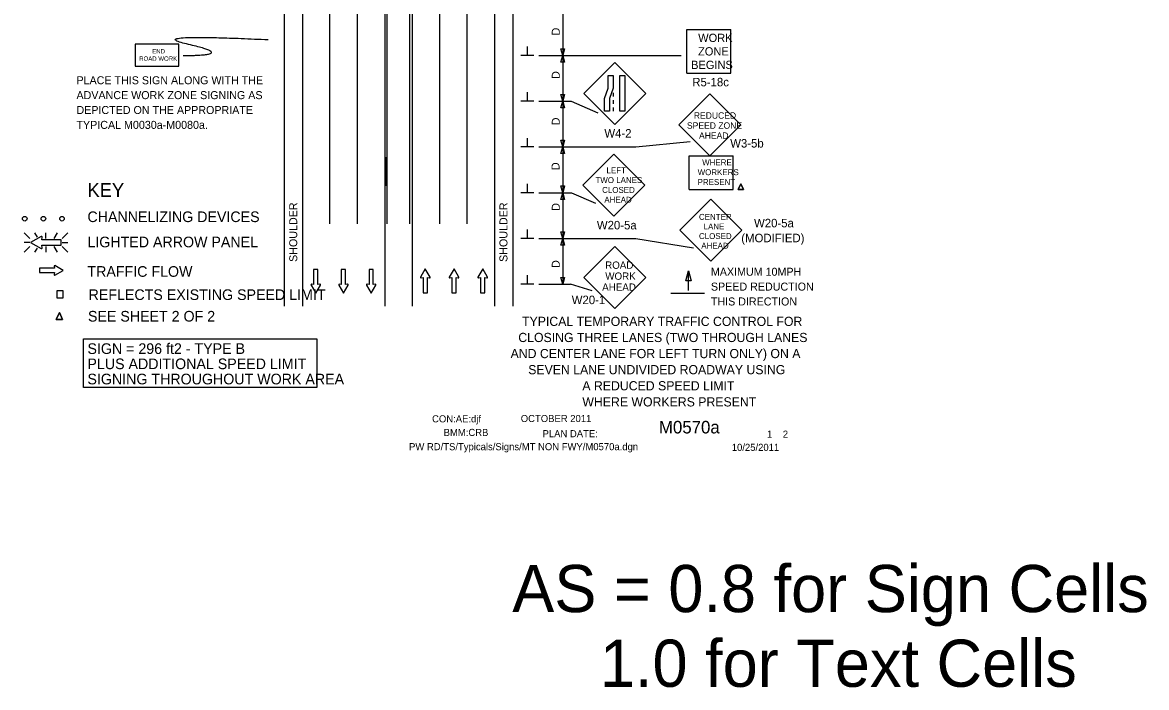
# Model space of a CAD drawing. Extents: x 16724 to 18475, y 5726 to 6929.
# Drawn here: x 16732 to 17716, y 5726 to 6308 of the extents above; entities that cross this region are included whole.
import ezdxf

# ---------------------------------------------------------------- set-up
doc = ezdxf.new("R2010")
doc.units = 0
for name, color, linetype in [('ALI_LEGAL_EX', 7, 'Continuous'), ('BORDER', 7, 'Continuous'), ('BORDER_SIGNAL_WO', 7, 'Continuous'), ('Level 3', 7, 'Continuous'), ('MT_SCRATCH_LEVEL_E', 7, 'Continuous'), ('PAVT_EDGE_EX', 7, 'Continuous'), ('TRAFFIC_SIGNS_PR', 7, 'Continuous'), ('TYPICAL_TEXT_DIMEN_EX', 7, 'Continuous'), ('TYPICAL_TEXT_DIMEN_PR', 7, 'Continuous')]:
    doc.layers.add(name, color=color, linetype=linetype)

msp = doc.modelspace()

# ---------------------------------------------------------------- linework, layer by layer
at = {"layer": 'ALI_LEGAL_EX'}
for p, q in [((17001.36, 6131.68), (17001.36, 6928.96)), ((17025.36, 6131.68), (17025.36, 6928.96)), ((17051.36, 6131.68), (17051.36, 6928.96)), ((17071.36, 6131.68), (17071.36, 6928.96)), ((17097.36, 6131.68), (17097.36, 6928.96)), ((17121.36, 6131.68), (17121.36, 6928.96))]:
    msp.add_line(p, q, dxfattribs=at)
for points in [[(17001.36, 6231.68), (17001.36, 6256.68)], [(17025.36, 6231.68), (17025.36, 6256.68)], [(17051.36, 6231.68), (17051.36, 6256.68)], [(17071.36, 6231.68), (17071.36, 6256.68)], [(17097.36, 6231.68), (17097.36, 6256.68)], [(17121.36, 6231.68), (17121.36, 6256.68)], [(17001.36, 6131.68), (17001.36, 6156.68)], [(17025.36, 6131.68), (17025.36, 6156.68)], [(17051.36, 6131.68), (17051.36, 6156.68)], [(17071.36, 6131.68), (17071.36, 6156.68)], [(17097.36, 6131.68), (17097.36, 6156.68)], [(17121.36, 6131.68), (17121.36, 6156.68)]]:
    msp.add_lwpolyline(points, dxfattribs=at)
at = {"layer": 'Level 3'}
msp.add_line((17268.9, 6118.89), (17319.36, 6110.64), dxfattribs=at)
at = {"layer": 'MT_SCRATCH_LEVEL_E'}
for p, q in [((16760.32, 6092.83), (16747.06, 6092.83)), ((16747.06, 6092.83), (16747.06, 6089.09)), ((16760.32, 6092.83), (16747.06, 6092.83)), ((16747.06, 6092.83), (16747.06, 6089.09)), ((16747.06, 6089.09), (16760.32, 6089.09)), ((16747.06, 6089.09), (16760.32, 6089.09)), ((16760, 6094.61), (16760.32, 6092.83)), ((16760, 6094.61), (16760.32, 6092.83)), ((16760.32, 6089.09), (16760, 6087.31)), ((16760.32, 6089.09), (16760, 6087.31)), ((16767.93, 6090.98), (16760.69, 6095.09)), ((16767.93, 6090.98), (16760.69, 6095.09)), ((16760.69, 6086.83), (16767.93, 6090.98)), ((16760.69, 6086.83), (16767.93, 6090.98)), ((16990.77, 6091.79), (16987.03, 6091.79)), ((16987.03, 6091.79), (16987.03, 6078.53)), ((16990.77, 6091.79), (16987.03, 6091.79)), ((16987.03, 6091.79), (16987.03, 6078.53)), ((16990.77, 6078.53), (16990.77, 6091.79)), ((16990.77, 6078.53), (16990.77, 6091.79)), ((17015.03, 6091.79), (17011.28, 6091.79)), ((17011.28, 6091.79), (17011.28, 6078.53)), ((17015.03, 6091.79), (17011.28, 6091.79)), ((17011.28, 6091.79), (17011.28, 6078.53)), ((17015.03, 6078.53), (17015.03, 6091.79)), ((17015.03, 6078.53), (17015.03, 6091.79)), ((17039.28, 6091.79), (17035.54, 6091.79)), ((17035.54, 6091.79), (17035.54, 6078.53)), ((17039.28, 6091.79), (17035.54, 6091.79)), ((17035.54, 6091.79), (17035.54, 6078.53)), ((17039.28, 6078.53), (17039.28, 6091.79)), ((17039.28, 6078.53), (17039.28, 6091.79)), ((17084.79, 6092.25), (17080.68, 6085.01)), ((17084.79, 6092.25), (17080.68, 6085.01)), ((17088.94, 6085.01), (17084.79, 6092.25)), ((17088.94, 6085.01), (17084.79, 6092.25)), ((17109.88, 6092.25), (17105.77, 6085.01)), ((17109.88, 6092.25), (17105.77, 6085.01)), ((17114.03, 6085.01), (17109.88, 6092.25)), ((17114.03, 6085.01), (17109.88, 6092.25)), ((17134.97, 6092.25), (17130.86, 6085.01)), ((17134.97, 6092.25), (17130.86, 6085.01)), ((17139.12, 6085.01), (17134.97, 6092.25)), ((17139.12, 6085.01), (17134.97, 6092.25)), ((16984.77, 6078.16), (16988.92, 6070.92)), ((16984.77, 6078.16), (16988.92, 6070.92)), ((16987.03, 6078.53), (16985.25, 6078.85)), ((16987.03, 6078.53), (16985.25, 6078.85)), ((16988.92, 6070.92), (16993.03, 6078.16)), ((16988.92, 6070.92), (16993.03, 6078.16)), ((16992.55, 6078.85), (16990.77, 6078.53)), ((16992.55, 6078.85), (16990.77, 6078.53)), ((17009.03, 6078.16), (17013.17, 6070.92)), ((17009.03, 6078.16), (17013.17, 6070.92)), ((17011.28, 6078.53), (17009.51, 6078.85)), ((17011.28, 6078.53), (17009.51, 6078.85)), ((17013.17, 6070.92), (17017.28, 6078.16)), ((17013.17, 6070.92), (17017.28, 6078.16)), ((17016.8, 6078.85), (17015.03, 6078.53)), ((17016.8, 6078.85), (17015.03, 6078.53)), ((17033.28, 6078.16), (17037.43, 6070.92)), ((17033.28, 6078.16), (17037.43, 6070.92)), ((17035.54, 6078.53), (17033.76, 6078.85)), ((17035.54, 6078.53), (17033.76, 6078.85)), ((17037.43, 6070.92), (17041.54, 6078.16)), ((17037.43, 6070.92), (17041.54, 6078.16)), ((17041.06, 6078.85), (17039.28, 6078.53)), ((17041.06, 6078.85), (17039.28, 6078.53)), ((17081.16, 6084.32), (17082.94, 6084.64)), ((17081.16, 6084.32), (17082.94, 6084.64)), ((17082.94, 6084.64), (17082.94, 6071.38)), ((17082.94, 6084.64), (17082.94, 6071.38)), ((17086.68, 6071.38), (17086.68, 6084.64)), ((17086.68, 6084.64), (17088.46, 6084.32)), ((17086.68, 6071.38), (17086.68, 6084.64)), ((17086.68, 6084.64), (17088.46, 6084.32)), ((17106.25, 6084.32), (17108.03, 6084.64)), ((17106.25, 6084.32), (17108.03, 6084.64)), ((17108.03, 6084.64), (17108.03, 6071.38)), ((17108.03, 6084.64), (17108.03, 6071.38)), ((17111.77, 6071.38), (17111.77, 6084.64)), ((17111.77, 6084.64), (17113.55, 6084.32)), ((17111.77, 6071.38), (17111.77, 6084.64)), ((17111.77, 6084.64), (17113.55, 6084.32)), ((17131.34, 6084.32), (17133.12, 6084.64)), ((17131.34, 6084.32), (17133.12, 6084.64)), ((17133.12, 6084.64), (17133.12, 6071.38)), ((17133.12, 6084.64), (17133.12, 6071.38)), ((17136.86, 6071.38), (17136.86, 6084.64)), ((17136.86, 6084.64), (17138.64, 6084.32)), ((17136.86, 6071.38), (17136.86, 6084.64)), ((17136.86, 6084.64), (17138.64, 6084.32)), ((17082.94, 6071.38), (17086.68, 6071.38)), ((17082.94, 6071.38), (17086.68, 6071.38)), ((17108.03, 6071.38), (17111.77, 6071.38)), ((17108.03, 6071.38), (17111.77, 6071.38)), ((17133.12, 6071.38), (17136.86, 6071.38)), ((17133.12, 6071.38), (17136.86, 6071.38))]:
    msp.add_line(p, q, dxfattribs=at)
for centre, start, end in [((16760.46, 6094.68), 60.42484, 189.96381), ((16760.46, 6094.68), 60.42484, 189.96381), ((16760.46, 6087.24), 170.03619, 299.77312), ((16760.46, 6087.24), 170.03619, 299.77312), ((16985.18, 6078.38), 80.03619, 209.77312), ((16985.18, 6078.38), 80.03619, 209.77312), ((16992.62, 6078.39), 330.42484, 99.96381), ((16992.62, 6078.39), 330.42484, 99.96381), ((17009.44, 6078.38), 80.03619, 209.77312), ((17009.44, 6078.38), 80.03619, 209.77312), ((17016.88, 6078.39), 330.42484, 99.96381), ((17016.88, 6078.39), 330.42484, 99.96381), ((17033.69, 6078.38), 80.03619, 209.77312), ((17033.69, 6078.38), 80.03619, 209.77312), ((17041.13, 6078.39), 330.42484, 99.96381), ((17041.13, 6078.39), 330.42484, 99.96381), ((17081.09, 6084.78), 150.42484, 279.96381), ((17081.09, 6084.78), 150.42484, 279.96381), ((17088.53, 6084.78), 260.03619, 29.77312), ((17088.53, 6084.78), 260.03619, 29.77312), ((17106.18, 6084.78), 150.42484, 279.96381), ((17106.18, 6084.78), 150.42484, 279.96381), ((17113.62, 6084.78), 260.03619, 29.77312), ((17113.62, 6084.78), 260.03619, 29.77312), ((17131.27, 6084.78), 150.42484, 279.96381), ((17131.27, 6084.78), 150.42484, 279.96381), ((17138.71, 6084.78), 260.03619, 29.77312), ((17138.71, 6084.78), 260.03619, 29.77312)]:
    msp.add_arc(centre, 0.463, start, end, dxfattribs=at)
at = {"layer": 'PAVT_EDGE_EX'}
for p, q in [((16961.36, 6924.76), (16961.36, 6059.7)), ((16977.36, 6924.76), (16977.36, 6059.7)), ((17049.36, 6924.76), (17049.36, 6059.7)), ((17073.36, 6924.76), (17073.36, 6059.7)), ((17145.36, 6924.76), (17145.36, 6059.7)), ((17161.36, 6924.76), (17161.36, 6059.7))]:
    msp.add_line(p, q, dxfattribs=at)
for points in [[(17025.36, 6164.93), (17025.36, 6189.93)], [(17050.36, 6164.93), (17050.36, 6189.93)]]:
    msp.add_lwpolyline(points, dxfattribs=at)
at = {"layer": 'TRAFFIC_SIGNS_PR'}
for p, q in [((17313.56, 6263.32), (17313.56, 6301.72)), ((17313.56, 6301.72), (17351.96, 6301.72)), ((17351.96, 6263.32), (17351.96, 6301.72)), ((17250.5, 6272.84), (17223.35, 6245.69)), ((17277.65, 6245.69), (17250.5, 6272.84)), ((17313.56, 6263.32), (17351.96, 6263.32)), ((17223.35, 6245.69), (17250.5, 6218.54)), ((17249.25, 6246.18), (17249.25, 6242.98)), ((17250.5, 6218.54), (17277.65, 6245.69)), ((17333.65, 6245.44), (17306.5, 6218.29)), ((17360.8, 6218.29), (17333.65, 6245.44)), ((17249.25, 6239.78), (17249.25, 6236.58)), ((17249.25, 6233.38), (17249.25, 6230.18)), ((17306.5, 6218.29), (17333.65, 6191.14)), ((17333.65, 6191.14), (17360.8, 6218.29)), ((17249.78, 6192.54), (17222.62, 6165.39)), ((17276.93, 6165.39), (17249.78, 6192.54)), ((17315.7, 6191.14), (17354.1, 6191.14)), ((17315.7, 6161.82), (17315.7, 6191.14)), ((17354.1, 6161.82), (17354.1, 6191.14)), ((17222.62, 6165.39), (17249.78, 6138.23)), ((17249.78, 6138.23), (17276.93, 6165.39)), ((17315.7, 6161.82), (17354.1, 6161.82)), ((17334.64, 6153.3), (17307.49, 6126.15)), ((17361.8, 6126.15), (17334.64, 6153.3)), ((16733.68, 6123.85), (16738.62, 6118.92)), ((16745.44, 6120.03), (16743.24, 6123.85)), ((16752.76, 6118.92), (16752.76, 6123.85)), ((16760, 6118.92), (16762.85, 6123.85)), ((16766.91, 6118.92), (16771.85, 6123.85)), ((17307.49, 6126.15), (17334.64, 6098.99)), ((17334.64, 6098.99), (17361.8, 6126.15)), ((16738.62, 6115.36), (16733.68, 6115.36)), ((16733.68, 6106.87), (16738.62, 6111.8)), ((16743.19, 6106.87), (16745.31, 6110.53)), ((16752.76, 6111.8), (16752.76, 6106.87)), ((16762.89, 6106.87), (16760.04, 6111.8)), ((16766.91, 6115.36), (16771.85, 6115.36)), ((16766.91, 6111.8), (16771.85, 6106.87)), ((17250.59, 6111.96), (17223.44, 6084.81)), ((17277.74, 6084.81), (17250.59, 6111.96)), ((17223.44, 6084.81), (17250.59, 6057.66)), ((17250.59, 6057.66), (17277.74, 6084.81))]:
    msp.add_line(p, q, dxfattribs=at)
for points in [[(16830.82, 6269.48), (16869.22, 6269.48), (16869.22, 6288.68), (16830.82, 6288.68)], [(17249.25, 6261.43), (17249.25, 6250.25), (17245.91, 6241.36), (17245.91, 6230.18), (17241.42, 6230.18), (17241.42, 6241.36), (17244.76, 6250.25), (17244.76, 6261.43)], [(17259.39, 6261.43), (17259.39, 6230.18), (17254.9, 6230.18), (17254.9, 6261.43)], [(16762.39, 6066.92), (16767.98, 6066.92), (16767.98, 6073.09), (16762.39, 6073.09)]]:
    msp.add_lwpolyline(points, close=True, dxfattribs=at)
for points in [[(17360.85, 6166.76), (17358.62, 6161.82)], [(17358.62, 6161.82), (17360.85, 6166.76)], [(17363.09, 6161.82), (17360.85, 6166.76)], [(17360.85, 6166.76), (17363.09, 6161.82)], [(17358.62, 6161.82), (17363.09, 6161.82)], [(17363.09, 6161.82), (17358.62, 6161.82)], [(16748.69, 6120.64), (16739.4, 6115.36), (16748.69, 6110.04)], [(16749.57, 6110.67), (16749.17, 6112.93), (16766.18, 6112.93), (16766.18, 6117.74), (16749.17, 6117.74), (16749.57, 6120.02)], [(16764.63, 6054.22), (16761.84, 6048.05)], [(16761.84, 6048.05), (16764.63, 6054.22)], [(16767.43, 6048.05), (16764.63, 6054.22)], [(16764.63, 6054.22), (16767.43, 6048.05)], [(16761.84, 6048.05), (16767.43, 6048.05)], [(16767.43, 6048.05), (16761.84, 6048.05)]]:
    msp.add_lwpolyline(points, dxfattribs=at)
for centre in [(16734.3, 6136.14), (16750.6, 6136.14), (16766.9, 6136.14)]:
    msp.add_circle(centre, 2, dxfattribs=at)
for centre, radius, start, end in [((16748.98, 6120.11), 0.598, 350.73078, 118.89165), ((16748.98, 6110.56), 0.597, 241.48329, 9.95933)]:
    msp.add_arc(centre, radius, start, end, dxfattribs=at)
msp.add_open_spline([(16872.81, 6278.85), (16920.05, 6278.85), (16835.03, 6298.2), (16947.32, 6292.71)], degree=2, dxfattribs=at)
at = {"layer": 'TYPICAL_TEXT_DIMEN_EX'}
msp.add_lwpolyline([(16785.8, 6031.01), (16989.79, 6031.01), (16989.79, 5988.44), (16785.8, 5988.44)], close=True, dxfattribs=at)
at = {"layer": 'TYPICAL_TEXT_DIMEN_PR'}
for p, q in [((17204.99, 6318.89), (17204.99, 6278.89)), ((17174.11, 6278.89), (17174.11, 6286.68)), ((17204.99, 6278.89), (17203.42, 6284.75)), ((17203.42, 6284.75), (17204.99, 6284.75)), ((17204.99, 6284.75), (17206.56, 6284.75)), ((17206.56, 6284.75), (17204.99, 6278.89)), ((17179.74, 6278.89), (17168.49, 6278.89)), ((17183.99, 6278.89), (17308.55, 6278.89)), ((17203.42, 6273.03), (17204.99, 6278.89)), ((17204.99, 6278.89), (17204.99, 6198.89)), ((17204.99, 6278.89), (17206.56, 6273.03)), ((17204.99, 6273.03), (17203.42, 6273.03)), ((17206.56, 6273.03), (17204.99, 6273.03)), ((17174.11, 6238.89), (17174.11, 6246.68)), ((17179.74, 6238.89), (17168.49, 6238.89)), ((17183.99, 6238.89), (17212.39, 6238.89)), ((17204.99, 6238.89), (17203.42, 6244.75)), ((17203.42, 6244.75), (17204.99, 6244.75)), ((17203.42, 6233.03), (17204.99, 6238.89)), ((17204.99, 6244.75), (17206.56, 6244.75)), ((17206.56, 6244.75), (17204.99, 6238.89)), ((17204.99, 6238.89), (17206.56, 6233.03)), ((17212.39, 6238.89), (17235.63, 6228.67)), ((17204.99, 6233.03), (17203.42, 6233.03)), ((17206.56, 6233.03), (17204.99, 6233.03)), ((17204.99, 6218.89), (17204.99, 6168.89)), ((17174.11, 6198.89), (17174.11, 6206.68)), ((17179.74, 6198.89), (17168.49, 6198.89)), ((17183.99, 6198.89), (17268.9, 6198.89)), ((17204.99, 6198.89), (17203.42, 6204.75)), ((17203.42, 6204.75), (17204.99, 6204.75)), ((17203.42, 6193.03), (17204.99, 6198.89)), ((17204.99, 6204.75), (17206.56, 6204.75)), ((17206.56, 6204.75), (17204.99, 6198.89)), ((17204.99, 6198.89), (17206.56, 6193.03)), ((17268.9, 6198.89), (17316.64, 6203.69)), ((17204.99, 6193.03), (17203.42, 6193.03)), ((17206.56, 6193.03), (17204.99, 6193.03)), ((17174.11, 6158.89), (17174.11, 6166.68)), ((17204.99, 6168.89), (17204.99, 6118.89)), ((17179.74, 6158.89), (17168.49, 6158.89)), ((17183.99, 6158.89), (17212.82, 6158.89)), ((17204.99, 6158.89), (17203.42, 6164.75)), ((17203.42, 6164.75), (17204.99, 6164.75)), ((17203.42, 6153.03), (17204.99, 6158.89)), ((17204.99, 6164.75), (17206.56, 6164.75)), ((17206.56, 6164.75), (17204.99, 6158.89)), ((17204.99, 6158.89), (17206.56, 6153.03)), ((17212.82, 6158.89), (17233.78, 6149.67)), ((17204.99, 6153.03), (17203.42, 6153.03)), ((17206.56, 6153.03), (17204.99, 6153.03)), ((17179.74, 6118.89), (17168.49, 6118.89)), ((17174.11, 6118.89), (17174.11, 6126.68)), ((17183.99, 6118.89), (17268.9, 6118.89)), ((17204.99, 6118.89), (17203.42, 6124.75)), ((17203.42, 6124.75), (17204.99, 6124.75)), ((17203.42, 6113.03), (17204.99, 6118.89)), ((17204.99, 6124.75), (17206.56, 6124.75)), ((17206.56, 6124.75), (17204.99, 6118.89)), ((17204.99, 6118.89), (17204.99, 6078.89)), ((17204.99, 6118.89), (17206.56, 6113.03)), ((17204.99, 6113.03), (17203.42, 6113.03)), ((17206.56, 6113.03), (17204.99, 6113.03)), ((17312.61, 6081.69), (17314.97, 6090.49)), ((17314.97, 6073.36), (17314.97, 6090.49)), ((17314.97, 6090.49), (17317.32, 6081.69)), ((17179.74, 6078.89), (17168.49, 6078.89)), ((17174.11, 6078.89), (17174.11, 6086.68)), ((17183.99, 6078.89), (17211.79, 6078.89)), ((17204.99, 6078.89), (17203.42, 6084.75)), ((17203.42, 6084.75), (17204.99, 6084.75)), ((17204.99, 6084.75), (17206.56, 6084.75)), ((17206.56, 6084.75), (17204.99, 6078.89)), ((17230.7, 6073.14), (17211.79, 6078.89)), ((17314.97, 6081.69), (17312.61, 6081.69)), ((17317.32, 6081.69), (17314.97, 6081.69)), ((17329.14, 6070.86), (17299.7, 6070.86))]:
    msp.add_line(p, q, dxfattribs=at)

# ---------------------------------------------------------------- texts
at = {"layer": 'BORDER'}
for s, height, p in [('TYPICAL TEMPORARY TRAFFIC CONTROL FOR', 8.0313, (17169.43, 6042.37)), ('CLOSING THREE LANES (TWO THROUGH LANES', 8.0313, (17166.13, 6028.29)), ('AND CENTER LANE FOR LEFT TURN ONLY) ON A', 8.0313, (17159.4, 6014.22)), ('SEVEN LANE UNDIVIDED ROADWAY USING ', 8.0313, (17174.82, 6000.14)), ('A REDUCED SPEED LIMIT', 8.0313, (17222.18, 5986.06)), ('WHERE WORKERS PRESENT', 8.0313, (17222.18, 5971.99)), ('PLAN DATE:', 6.2, (17187.35, 5945.07))]:
    msp.add_text(s, height=height, dxfattribs=at).set_placement(p)
at = {"layer": 'BORDER_SIGNAL_WO'}
for s, height, p in [('CON:AE:djf', 6.2, (17090.69, 5958.06)), ('    OCTOBER 2011    ', 6.2, (17159.08, 5958.34)), ('BMM:CRB   ', 6.2, (17100.81, 5946.17)), ('    M0570a   ', 11, (17272.86, 5948.38)), (' 1    2 ', 6.2, (17381.45, 5944.7)), ('PW RD/TS/Typicals/Signs/MT NON FWY/M0570a.dgn    ', 6.2, (17070.55, 5933.71)), ('10/25/2011    ', 6.2, (17352.93, 5933.13)), ('AS = 0.8 for Sign Cells', 41.2877, (17160.83, 5792.11)), ('     1.0 for Text Cells', 41.2877, (17160.83, 5726.82))]:
    msp.add_text(s, height=height, dxfattribs=at).set_placement(p)
at = {"layer": 'TRAFFIC_SIGNS_PR'}
for s, height, p in [('WORK', 7.217, (17323.56, 6290.68)), ('ZONE', 7.217, (17323.44, 6278.87)), ('ROAD WORK', 3.831, (16834.43, 6274.22)), ('END', 3.831, (16845.82, 6280.61)), ('BEGINS', 7.217, (17317.37, 6267.06)), ('PLACE THIS SIGN ALONG WITH THE', 7, (16779.54, 6253.7)), ('R5-18c', 7.44, (17318.37, 6251.88)), ('ADVANCE WORK ZONE SIGNING AS', 7, (16779.54, 6240.7)), ('DEPICTED ON THE APPROPRIATE', 7, (16779.54, 6227.7)), ('REDUCED', 5.6, (17319.71, 6223.6)), ('TYPICAL M0030a-M0080a.', 7, (16779.54, 6214.7)), ('SPEED ZONE', 5.6, (17313.7, 6214.8)), ('W4-2', 7.44, (17241.46, 6207.1)), ('AHEAD', 5.6, (17324.26, 6206)), ('W3-5b', 7.44, (17351.56, 6198.37)), ('WHERE', 5.2, (17327.02, 6182.82)), ('LEFT', 5.2, (17243.31, 6175.92)), ('WORKERS', 5.2, (17323.09, 6174.22)), ('TWO LANES', 5.2, (17233.64, 6167.32)), ('PRESENT', 5.2, (17323.02, 6165.62)), ('CLOSED', 5.2, (17239.49, 6158.72)), ('AHEAD', 5.2, (17241.43, 6150.12)), ('CENTER', 5.2, (17324.22, 6135.15)), ('W20-5a', 7.44, (17234.91, 6126.79)), ('LANE', 5.2, (17328.3, 6126.75)), ('W20-5a', 7.44, (17372.39, 6128.59)), ('CLOSED', 5.2, (17324.22, 6118.35)), ('(MODIFIED)', 7.44, (17361.25, 6115.55)), ('AHEAD', 5.2, (17326.25, 6109.95)), ('ROAD', 6.4, (17242.13, 6092.35)), ('WORK', 6.4, (17242.24, 6082.75)), ('AHEAD', 6.4, (17239.55, 6073.15)), ('W20-1', 7.44, (17212.88, 6061.44))]:
    msp.add_text(s, height=height, dxfattribs=at).set_placement(p)
at = {"layer": 'TYPICAL_TEXT_DIMEN_EX'}
for s, height, p in [('KEY', 12, (16789.14, 6155.25)), ('CHANNELIZING DEVICES', 9.3, (16789.14, 6133.2)), ('LIGHTED ARROW PANEL', 9.3, (16789.14, 6111.15)), ('TRAFFIC FLOW', 9.3, (16789.14, 6085.35)), ('REFLECTS EXISTING SPEED LIMIT', 9.3, (16790.15, 6065.08)), ('SEE SHEET 2 OF 2', 9.3, (16789.6, 6046.22)), ('SIGN = 296 ft2 - TYPE B', 9.3, (16789.14, 6017.9)), ('PLUS ADDITIONAL SPEED LIMIT', 9.3, (16789.14, 6004.6)), ('SIGNING THROUGHOUT WORK AREA', 9.3, (16789.14, 5991.3))]:
    msp.add_text(s, height=height, dxfattribs=at).set_placement(p)
at = {"layer": 'TYPICAL_TEXT_DIMEN_PR'}
for s, p in [('D', (17202.43, 6296.43)), ('D', (17202.43, 6258.39)), ('D', (17202.43, 6217.84)), ('D', (17202.21, 6178.63)), ('SHOULDER', (16972.73, 6098.36)), ('SHOULDER', (17156.64, 6098.36)), ('D', (17202.43, 6143.11)), ('D', (17202.43, 6093.11))]:
    msp.add_text(s, height=7, rotation=90, dxfattribs=at).set_placement(p)
for s, p in [('MAXIMUM 10MPH ', (17334.66, 6086.28)), ('SPEED REDUCTION', (17334.66, 6073.28)), ('THIS DIRECTION', (17334.66, 6060.28))]:
    msp.add_text(s, height=7, dxfattribs=at).set_placement(p)

doc.saveas('drawing.dxf')
